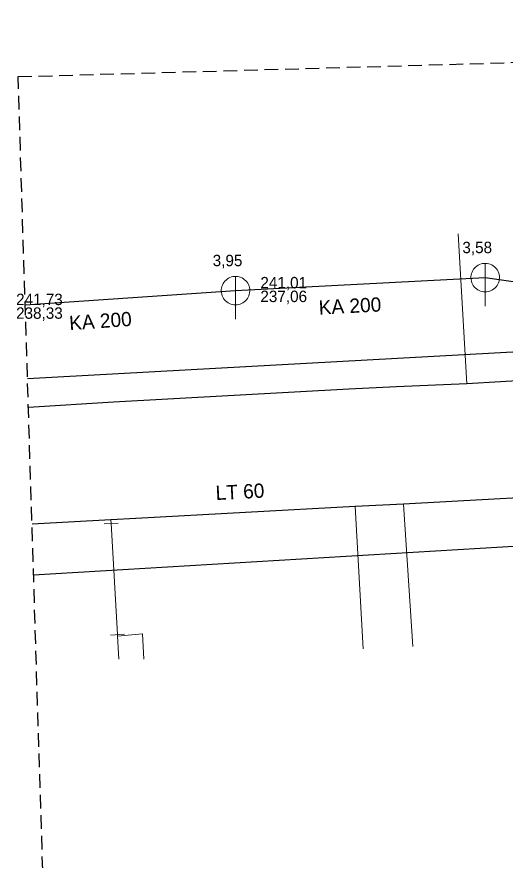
# Model space of a CAD drawing. Extents: x -777996 to -777727, y -976581 to -976199.
# Drawn here: x -777995.5 to -777961.3, y -976257.9 to -976198.8 of the extents above; entities that cross this region are included whole.
import ezdxf

# ---------------------------------------------------------------- set-up
doc = ezdxf.new("R2010")
doc.units = 0
doc.header["$LTSCALE"] = 0.32
doc.linetypes.add('MEDIUM_DASHED', pattern=[4.5, 3, -1.5])
for name, color, linetype, lineweight in [('1', 7, 'MEDIUM_DASHED', 25), ('13', 7, 'Continuous', 13), ('14', 7, 'Continuous', 25), ('17', 7, 'Continuous', 25), ('22', 7, 'Continuous', 13), ('34', 7, 'Continuous', 13)]:
    doc.layers.add(name, color=color, linetype=linetype, lineweight=lineweight)

msp = doc.modelspace()

# ---------------------------------------------------------------- linework, layer by layer
at = {"layer": '1'}
msp.add_lwpolyline([(-777995.417, -976203.033), (-777848.18, -976198.846), (-777864.927, -976230.247), (-777726.762, -976491.225), (-777789.565, -976581.242), (-777941.686, -976558.215), (-777989.136, -976405.396)], close=True, dxfattribs=at)
at = {"layer": '13'}
for p, q in [((-777963.963, -976224.532), (-777964.581, -976214.048)), ((-777971.234, -976243.1), (-777971.795, -976233.14)), ((-777967.749, -976242.929), (-777968.399, -976232.955))]:
    msp.add_line(p, q, dxfattribs=at)
for points in [[(-777988.352, -976243.81), (-777988.443, -976242.207), (-777988.449, -976242.102), (-777988.894, -976234.326)], [(-777986.6, -976243.823), (-777986.703, -976242.047), (-777988.443, -976242.207)]]:
    msp.add_lwpolyline(points, dxfattribs=at)
at = {"layer": '14'}
for p, q in [((-777980.177, -976218.017), (-777962.675, -976217.105)), ((-777962.675, -976217.105), (-777935.509, -976220.899)), ((-777994.921, -976219.008), (-777980.177, -976218.017)), ((-777994.761, -976224.174), (-777935.509, -976220.899)), ((-777994.334, -976237.923), (-777946.791, -976235.083))]:
    msp.add_line(p, q, dxfattribs=at)
at = {"layer": '14', "lineweight": 13}
msp.add_line((-777988.908, -976234.069), (-777988.894, -976234.326), dxfattribs=at)
at = {"layer": '17'}
for points in [[(-777935.637, -976223.213), (-777950.839, -976223.756), (-777954.513, -976223.98), (-777963.963, -976224.532), (-777968.897, -976224.76), (-777972.243, -976224.917), (-777988.739, -976225.824), (-777994.698, -976226.192)], [(-777934.804, -976231.131), (-777950.365, -976231.976), (-777953.98, -976232.172), (-777953.982, -976232.172), (-777968.399, -976232.955), (-777971.795, -976233.14), (-777987.174, -976233.975), (-777988.908, -976234.069), (-777994.444, -976234.369)]]:
    msp.add_lwpolyline(points, dxfattribs=at)
at = {"layer": '22'}
for p, q in [((-777962.675, -976219.105), (-777962.674, -976216.105)), ((-777980.178, -976220.017), (-777980.177, -976217.017))]:
    msp.add_line(p, q, dxfattribs=at)
for points in [[(-777961.675, -976217.105), (-777961.68, -976216.996), (-777961.698, -976216.888), (-777961.728, -976216.782), (-777961.768, -976216.681), (-777961.82, -976216.584), (-777961.882, -976216.494), (-777961.954, -976216.411), (-777962.034, -976216.337), (-777962.122, -976216.271), (-777962.216, -976216.216), (-777962.316, -976216.171), (-777962.421, -976216.138), (-777962.528, -976216.116), (-777962.637, -976216.106), (-777962.747, -976216.108), (-777962.855, -976216.122), (-777962.962, -976216.147), (-777963.065, -976216.184), (-777963.163, -976216.233), (-777963.255, -976216.291), (-777963.341, -976216.36), (-777963.418, -976216.437), (-777963.487, -976216.523), (-777963.546, -976216.615), (-777963.594, -976216.713), (-777963.631, -976216.816), (-777963.657, -976216.923), (-777963.671, -976217.031), (-777963.674, -976217.141), (-777963.664, -976217.25), (-777963.643, -976217.357), (-777963.609, -976217.461), (-777963.565, -976217.561), (-777963.51, -976217.656), (-777963.444, -976217.744), (-777963.37, -976217.824), (-777963.287, -976217.896), (-777963.197, -976217.958), (-777963.101, -976218.01), (-777962.999, -976218.051), (-777962.894, -976218.081), (-777962.786, -976218.099), (-777962.676, -976218.105), (-777962.567, -976218.099), (-777962.459, -976218.081), (-777962.354, -976218.052), (-777962.252, -976218.011), (-777962.155, -976217.959), (-777962.065, -976217.897), (-777961.982, -976217.826), (-777961.907, -976217.746), (-777961.842, -976217.658), (-777961.786, -976217.564), (-777961.742, -976217.464), (-777961.708, -976217.36), (-777961.686, -976217.252), (-777961.676, -976217.143)], [(-777979.178, -976218.017), (-777979.183, -976217.908), (-777979.201, -976217.8), (-777979.231, -976217.694), (-777979.271, -976217.593), (-777979.323, -976217.496), (-777979.385, -976217.406), (-777979.457, -976217.323), (-777979.537, -976217.249), (-777979.625, -976217.183), (-777979.719, -976217.128), (-777979.819, -976217.083), (-777979.924, -976217.05), (-777980.031, -976217.028), (-777980.14, -976217.018), (-777980.25, -976217.02), (-777980.358, -976217.034), (-777980.465, -976217.059), (-777980.568, -976217.096), (-777980.666, -976217.145), (-777980.758, -976217.203), (-777980.844, -976217.272), (-777980.921, -976217.349), (-777980.99, -976217.435), (-777981.049, -976217.527), (-777981.097, -976217.625), (-777981.134, -976217.728), (-777981.16, -976217.835), (-777981.174, -976217.943), (-777981.177, -976218.053), (-777981.167, -976218.162), (-777981.146, -976218.269), (-777981.112, -976218.373), (-777981.068, -976218.473), (-777981.013, -976218.568), (-777980.947, -976218.656), (-777980.873, -976218.736), (-777980.79, -976218.808), (-777980.7, -976218.87), (-777980.604, -976218.922), (-777980.502, -976218.963), (-777980.397, -976218.993), (-777980.289, -976219.011), (-777980.179, -976219.017), (-777980.07, -976219.011), (-777979.962, -976218.993), (-777979.857, -976218.964), (-777979.755, -976218.923), (-777979.658, -976218.871), (-777979.568, -976218.809), (-777979.485, -976218.738), (-777979.41, -976218.658), (-777979.345, -976218.57), (-777979.289, -976218.476), (-777979.245, -976218.376), (-777979.211, -976218.272), (-777979.189, -976218.164), (-777979.179, -976218.055)]]:
    msp.add_lwpolyline(points, close=True, dxfattribs=at)
at = {"layer": '34'}
for p, q in [((-777989.393, -976234.355), (-777988.394, -976234.297)), ((-777988.948, -976242.131), (-777987.949, -976242.073))]:
    msp.add_line(p, q, dxfattribs=at)

# ---------------------------------------------------------------- texts
at = {"layer": '1'}
for s, p in [('3,58', (-777964.275, -976215.393)), ('3,95', (-777981.777, -976216.305))]:
    msp.add_text(s, height=0.8, dxfattribs=at).set_placement(p)
for s, rotation, p in [('KA 200', 3, (-777974.318, -976219.699)), ('KA 200', 4, (-777991.801, -976220.788)), ('LT 60 ', 3, (-777981.548, -976232.682))]:
    msp.add_text(s, height=1, rotation=rotation, dxfattribs=at).set_placement(p)
at = {"layer": '22'}
for s, p in [('241,01', (-777978.435, -976217.856)), ('237,06', (-777978.435, -976218.816)), ('241,73', (-777995.561, -976219.028)), ('238,33', (-777995.561, -976219.988))]:
    msp.add_text(s, height=0.8, dxfattribs=at).set_placement(p)

doc.saveas('drawing.dxf')
